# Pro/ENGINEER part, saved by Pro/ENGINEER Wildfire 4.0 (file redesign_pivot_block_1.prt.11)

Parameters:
  METRIC = "NO"

Other parameters: PITCH, DRILL_POINT_ANGLE, DRILL_DEPTH, DRILL_DIAMETER, THREAD_DIAMETER, THREADS_PER_INCH, THREAD_DEPTH, THREAD_LENGTH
